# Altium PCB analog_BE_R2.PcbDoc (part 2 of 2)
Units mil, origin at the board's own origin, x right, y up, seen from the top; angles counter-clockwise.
Board outline 3800 x 1200 mil, 2 copper layers (Top Layer, Bottom Layer), stack 62 mil thick; 98 components, 58 nets, 283 pads, 64 vias.
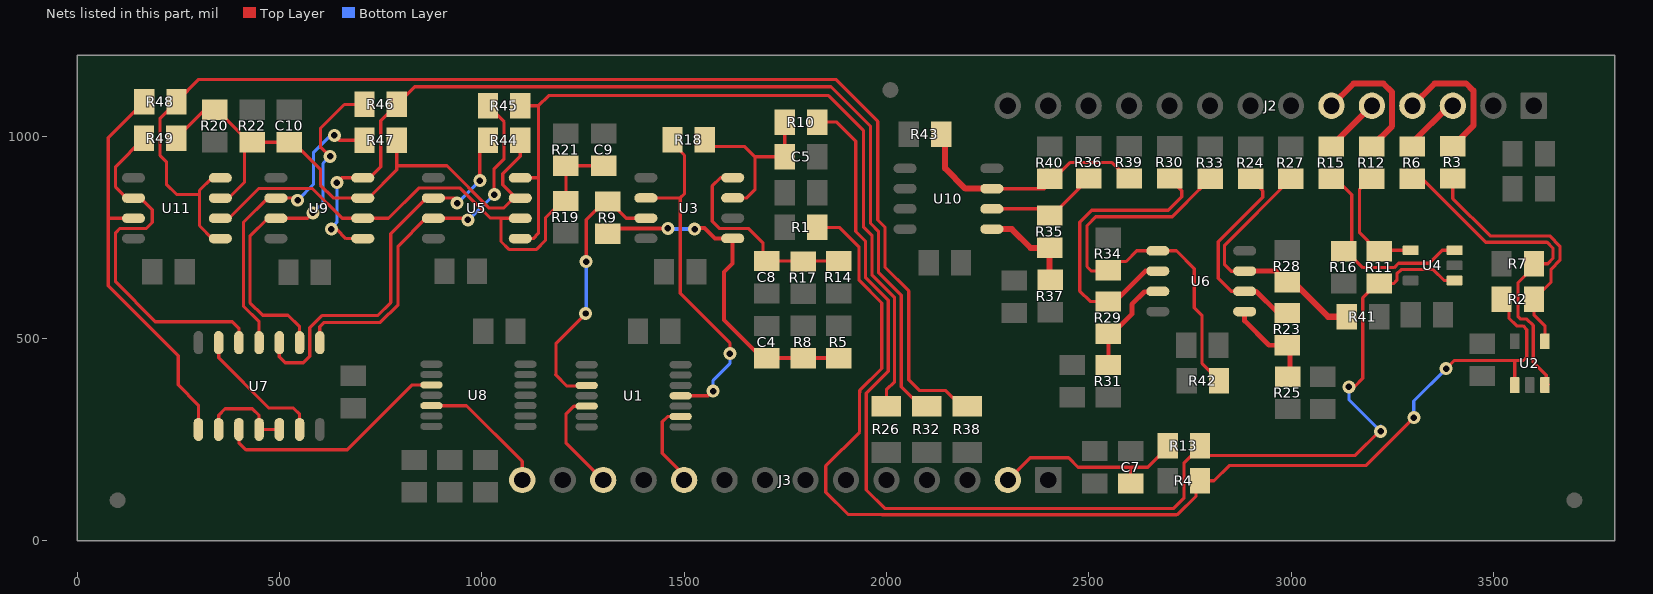
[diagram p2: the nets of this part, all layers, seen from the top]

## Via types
v1: diameter 32, hole 16, Top Layer to Bottom Layer, 54 vias
v2: diameter 40, hole 20, Top Layer to Bottom Layer, 10 vias

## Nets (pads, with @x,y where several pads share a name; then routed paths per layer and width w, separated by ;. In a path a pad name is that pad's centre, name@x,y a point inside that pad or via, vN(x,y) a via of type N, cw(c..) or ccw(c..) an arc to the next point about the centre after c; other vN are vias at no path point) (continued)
NetC4_1: C4.1 R5.1 R8.2 R9.2 U3.1 | length 903.4
  Top Layer w10: R9.2@1302.62,758.47 1315.94,771.8 v1(1459.66,771.8) ; v1(1525.84,770) 1528.22,772.37 1550.76,772.37 1576.02,747.11 U3.1@1620.06,747.11 1620.06,685 1598.69,663.64 1598.69,545.23 1690.27,453.65 C4.1@1690.27,450.96 ; R5.1@1882.6,451.05 1704.02,451.05 C4.1@1703.92,450.96 ; C4.1@1690.27,450.96 1690.27,437.3 C4.1@1703.92,450.96 ; C4.1@1690.27,450.96 C4.1@1703.92,450.96
  Bottom Layer w10: v1(1459.66,771.8) 1461.46,770 v1(1525.84,770)
NetC5_1: C5.1 R10.2 R18.2 U3.3 | length 445.7
  Top Layer w8: R18.2@1551.15,990.85 1567.95,974.05 1650,974.05 1675,949.05 ; U3.3@1620.06,847.11 1655,847.11 1675,867.12 1675,949.05 ; R10.2@1748.88,1034.49 C5.1@1748.88,949.05 1675,949.05
NetC8_1: C8.1 R14.1 R17.2 U3.4 | length 496.1
  Top Layer w8: U3.4@1620.06,897.11 1589.85,897.11 1569.66,876.93 1569.66,789.2 1587.06,771.8 1658.46,771.8 1695,735.26 C8.1@1695,712 ; C8.1@1703.92,691.26 R14.1@1882.6,691.27
NetC9_1: C9.1 R19.1 R21.2 U5.2 U9.2 U11.2 | length 1352.3
  Top Layer w8: U11.2@353.82,796.8 375.2,796.8 448.88,870.49 581.12,870.49 654.8,796.8 U9.2@705.78,796.8 769.39,796.8 844.06,871.47 946.69,871.47 1020.66,797.5 1049.02,797.5 1049.72,796.8 ; U5.2@1095.03,796.8 1049.72,796.8 ; C9.1@1301.58,926.62 R21.2@1207.81,926.62 1207.81,844.12 1203.32,839.63 1198.83,839.63 1157.4,798.2 1157.4,742.05 1135.27,719.92 1066.97,719.92 1047.45,739.44 1047.45,795.94 1048.32,796.8 1049.72,796.8
NetC10_1: C10.1 R20.1 R22.1 R44.2 R47.2 R49.1 U5.3 U9.3 U11.3 | length 1485.4
  Top Layer w8: R49.1@245,994.43 315.57,1065 R20.1@340.37,1065 344.75,1065 424.75,985 R22.1@432.65,985 C10.1@524.61,985 534.45,985 601.19,918.26 601.19,878.81 632.72,847.28 705.31,847.28 U9.3@705.78,846.8 720,846.8 790,916.8 790,926.62 ; U11.3@353.82,846.8 374.01,846.8 413.7,886.5 413.7,920 R22.1@413.7,975.48 ; R47.2@790,990 790,926.62 ; U5.3@1081.98,846.8 1078.34,846.8 1053.65,822.11 1018.5,822.11 913.99,926.62 790,926.62 ; U5.3@1095.03,846.8 1085.11,846.8 1051.9,880.02 1051.9,906.97 1095.03,950.1 R44.2@1095.03,989.91
NetR1_1: R1.1 R2.2 R4.1 U2.1 | length 3017.7
  Top Layer w8: R1.1@1828.88,774.42 1883.12,774.42 1932.38,725.16 1932.38,643.66 1932.5,643.54 1932.5,643.26 1988.25,587.52 1988.25,425.72 1934.13,371.59 1934.13,367.12 1933.58,366.57 1933.58,268.58 1850,185 1850,120 1905,65 1987.95,65 1988.82,64.13 2716.58,64.13 2717.45,65 2720,65 2764.96,109.96 2764.96,148.21 R4.1@2775,148.21 2809.37,148.21 2846.96,185.81 3184.86,185.81 v1(3303.46,304.42) ; v1(3383.1,425.42) 3403.08,445.4 3552.52,445.4 ; R2.2@3520,597.1 3528.49,597.1 3538.51,587.08 3538.51,550.03 3557.56,530.98 3573.27,530.98 3582.58,521.67 3582.58,453.69 3574.29,445.4 3552.52,445.4 ; U2.1@3552.52,384.67 3552.52,445.4
  Bottom Layer w8: v1(3303.46,304.42) 3303.09,304.79 3303.09,345.41 v1(3383.1,425.42)
NetR2_1: R2.1 R3.2 U2.4 | length 635.9
  Top Layer w8: R3.2@3399.66,895 3399.66,845.53 3491.82,753.36 3639.12,753.36 3664.32,728.16 3664.32,692.63 3642.39,670.7 3642.39,639.49 R2.1@3600,597.1 3600,558.55 3627.32,531.23 U2.4@3627.32,492.94
NetR6_2: R6.2 R7.2 U2.3 | length 856.8
  Top Layer w8: R6.2@3299.66,894.53 3323.79,894.53 3480.84,737.48 3632.55,737.48 3647.22,722.81 3647.22,697.99 3634,684.76 R7.2@3600,684.76 3600,676.41 3560.51,636.92 3560.51,554.74 3567.54,547.71 3582.79,547.71 3598.45,532.04 3598.45,441.29 3630.63,409.12 3630.63,391.16 U2.3@3635.85,385.94
  Top Layer w10: U2.3@3627.32,384.67 U2.3@3631.06,380.94
NetR9_1: R9.1 U1.3 U3.7 | length 705.5
  Top Layer w8: v1(1256.66,561.59) 1256.66,560.66 1183.13,487.13 1183.13,410.27 1182.86,410 1210.58,382.28 1257.66,382.28 U1.3@1259.2,383.82 ; v1(1258,690) 1258,793.1 1303.37,838.47 R9.1@1311.63,838.47 ; R9.1@1301.58,824.84 R9.1@1315.21,838.47 ; R9.1@1311.53,838.57 R9.1@1311.63,838.47 ; U3.7@1405.49,797.11 1356.57,797.11 R9.1@1315.21,838.47 ; R9.1@1311.63,838.47 R9.1@1315.21,838.47
  Bottom Layer w8: v1(1256.66,561.59) 1258,562.93 v1(1258,690)
NetR10_1: R10.1 R11.2 R13.1 U4.1 | length 3125.6
  Top Layer w8: R10.1@1828.88,1034.49 1877.17,1034.49 1924.1,987.56 1924.1,764.15 1948.25,740 1948.25,650.24 1948.51,649.98 1948.38,649.84 2004.13,594.09 2004.13,419.14 1950,365.02 1950,125.4 1995.4,80 2710,80 2735,105 2735,191.47 2754.42,210.89 3158.55,210.89 3217.66,270 v1(3221.33,270) ; v1(3142.99,380) 3156.08,380 3177.22,401.14 3177.22,600.04 3212.62,635.43 R11.2@3217.62,635.43 3253.05,635.43 3261.53,643.91 3261.53,659.54 3271.99,670 3351.35,670 3378.26,643.09 U4.1@3403.8,643.09
  Bottom Layer w8: v1(3142.99,380) 3142.99,348.34 3214.63,276.7 3221.33,283.41 v1(3221.33,270)
NetR11_1: R11.1 R12.2 U4.4 | length 295.9
  Top Layer w8: R12.2@3199.66,894.53 3199.66,890 3182.66,873 3173.59,873 3169.16,868.57 3169.16,760.6 3211.87,717.89 U4.4@3295.53,717.89
NetR15_2: R15.2 R16.2 U4.3 | length 530
  Top Layer w8: R15.2@3099.66,894.53 3110.13,894.53 3149.66,855 3149.66,740.43 3124.66,715.43 R16.2@3129.66,715.43 3136.96,715.43 3177.4,675 3254.54,675 3265.41,685.87 3341.21,685.87 3373.23,717.89 U4.3@3403.8,717.89
NetR18_1: R18.1 U1.11 U3.6 | length 875.3
  Top Layer w8: U3.6@1405.49,847.11 1490.42,847.11 ; R18.1@1471.15,990.85 1471.15,981.88 1500.84,952.19 1500.84,857.53 1490.42,847.11 ; U1.11@1491.48,358.23 1559.7,358.23 v1(1571.47,370) ; v1(1613.06,462.25) 1613.06,488.82 1490.42,611.45 1490.42,847.11
  Bottom Layer w8: v1(1571.47,370) 1571.47,396.18 1613.06,437.77 v1(1613.06,462.25)
NetR23_1: R23.1 R24.2 U6.2 | length 510.3
  Top Layer w8: U6.2@2885.16,616.37 2851.68,616.37 2819.71,648.34 2819.71,739.03 2929.66,848.98 2929.66,864.53 R24.2@2899.66,894.53
  Top Layer w12: U6.2@2885.16,616.37 2913.25,616.37 2966.52,563.1 R23.1@2990.51,563.1
NetR23_2: R23.2 R25.1 U6.1 | length 239.9
  Top Layer w12: U6.1@2885.16,566.37 2885.16,543.32 2945.38,483.1 R23.2@2990.51,483.1 2997.45,476.16 R25.1@2997.45,399.44
NetR26_2: R26.2 R45.1 U5.1 U5.4 | length 2027
  Top Layer w8: U5.1@1095.03,746.8 1127.41,746.8 1140,759.4 1140,883.41 1140,897.11 ; U5.4@1095.03,896.8 1139.69,896.8 1140,897.11 ; R45.1@1095.14,1075 1140,1075 ; R26.2@2000,331.89 2000,373.05 2020,393.05 2020,600.94 1964.13,656.81 1964.13,755 1943.1,776.02 1943.1,1013.93 1857.03,1100 1165,1100 1140,1075 ; 1140,897.11 1140,1075
NetR27_2: R27.2 R28.2 R41.2 U6.3 | length 635.9
  Top Layer w8: U6.3@2885.16,666.37 2884.77,665.98 2851.87,665.98 2835.58,682.27 2835.58,730.46 R27.2@2999.66,894.53
  Top Layer w12: U6.3@2885.16,666.37 2962.95,666.37 R28.2@2990.51,638.81
  Top Layer w15: R28.2@2990.51,638.81 3006.19,638.81 3091.4,553.6 R41.2@3137.62,553.6
NetR29_1: R29.1 R30.2 U6.6 | length 764
  Top Layer w8: R29.1@2548.35,591.37 2531.62,574.64 2531.62,591.37 2503.35,591.37 2477.66,617.07 2477.66,787.53 2506.78,816.65 2696.12,816.65 2729.66,850.18 2729.66,865 R30.2@2699.66,895
  Top Layer w12: R29.1@2548.35,591.37 2565.04,591.37 2640.04,666.37 U6.6@2670.59,666.37
NetR29_2: R29.2 R31.1 U6.7 | length 256.8
  Top Layer w10: R31.1@2548.35,434.41 R29.2@2548.35,511.37
  Top Layer w12: R29.2@2548.35,511.65 2565.09,528.39 2574.82,528.39 2606.43,560 2606.43,584.22 2637.62,615.41 2669.64,615.41 U6.7@2670.59,616.37
NetR32_2: R32.2 R46.1 U9.1 U9.4 | length 2492.4
  Top Layer w8: v1(628.43,770) 641.01,770 664.21,746.8 U9.1@705.78,746.8 ; v1(641.88,885) 653.68,896.8 U9.4@705.78,896.8 722.76,896.8 750,924.05 750,1038.08 R46.1@790,1078.07 833.97,1122.04 1862.96,1122.04 1960.55,1024.45 1960.55,784.45 1980,765 1980,663.39 2036.31,607.07 2036.31,380.65 2085.07,331.89 R32.2@2100,331.89
  Bottom Layer w8: v1(628.43,770) 631.44,770 636.23,774.79 636.23,781.03 641.88,786.68 v1(641.88,885)
NetR33_2: R33.2 R34.2 R42.2 U6.5 | length 1064.2
  Top Layer w8: R33.2@2799.76,894.53 2743.53,838.3 2743.53,838.12 2706.19,800.77 2517.35,800.77 2495.53,778.95 2495.53,677.52 2506.68,666.37 2546.02,666.37 R34.2@2548.35,668.7 2569.65,690 2592.11,690 2618.48,716.37 U6.5@2670.59,716.37 2716.72,716.37 2760.8,672.29 2760.8,575.37 2780,556.17 2780,437.9 R42.2@2821.94,395.95
NetR35_1: R35.1 R36.2 U10.2 | length 283.7
  Top Layer w8: U10.2@2260.46,820.15 2386.92,820.15 R35.1@2403.18,803.89 2408.98,809.69 2414.35,809.69 R36.2@2499.66,895
NetR35_2: R35.2 R37.1 U10.1 | length 241.6
  Top Layer w15: U10.1@2260.46,770.15 2309.65,770.15 2355.91,723.89 R35.2@2403.18,723.89 2403.18,646.29 R37.1@2404.66,644.81
NetR38_2: R38.2 R48.1 U11.1 U11.4 | length 3176.4
  Top Layer w8: U11.1@353.82,746.8 334.35,746.8 302.38,778.78 302.38,855.61 ; U11.4@353.82,896.8 333.36,896.8 302.38,865.82 302.38,855.61 ; R38.2@2199.66,331.89 2185.48,331.89 2146.21,371.16 2081.85,371.16 2055,398.01 2055,617.38 1996.31,676.07 1996.31,775 1978.68,792.63 1978.68,1036.32 1875,1140 300.63,1140 R48.1@245.63,1085 205,1044.37 205,951.88 220.58,936.3 220.58,880.83 245.81,855.61 302.38,855.61
NetR39_2: R39.2 R40.2 R43.2 U10.3 | length 618.7
  Top Layer w8: U10.3@2260.46,870.15 2389.73,870.15 R40.2@2403.18,883.6 ; R40.2@2403.18,894.53 R40.2@2403.18,883.6 ; R39.2@2599.66,895 2596.27,895 2556.27,935 2454.58,935 R40.2@2403.18,883.6
  Top Layer w15: R43.2@2135.22,1005 2145,995.22 2145,920 2194.85,870.15 U10.3@2260.46,870.15
NetR44_1: R44.1 U5.6 U7.3 | length 1026.9
  Top Layer w8: U7.3@499.66,489.57 499.66,454.62 514.46,439.82 558.61,439.82 574.66,455.87 574.66,526.66 603.29,555.29 603.85,555.29 605.26,556.71 743.05,556.71 775,588.66 775,758.79 863.01,846.8 U5.6@880.46,846.8 933.5,846.8 939,841.31 v1(939,834.19) ; v1(995,890) 995,1009.93 R44.1@1015.03,989.91
  Bottom Layer w8: v1(939,834.19) 939.19,834.19 v1(995,890)
NetR45_2: R45.2 U5.7 U7.1 | length 946.8
  Top Layer w8: U7.1@599.66,489.57 599.66,528.66 610.42,539.42 749.52,539.42 793,582.9 793,728.08 861.72,796.8 U5.7@880.46,796.8 961.62,796.8 v1(965.54,792.88) v1@968.51,795.85 ; R45.2@1015.14,1075 1055,1035.14 1055,943.58 1030,918.58 1030,864.54 1030.93,865.47 v1(1030.93,855.61)
  Bottom Layer w8: v1(965.54,792.88) 968.2,792.88 v1(1030.93,855.61)
NetR46_2: R46.2 U7.2 U9.7 | length 899.4
  Top Layer w8: U7.2@549.66,489.57 549.66,528.73 521.1,557.29 458.3,557.29 427,588.58 427,752.26 471.54,796.8 U9.7@491.21,796.8 569.51,796.8 v1(582.7,810) ; v1(625,950) 601.19,973.81 601.19,1018.75 660.51,1078.07 R46.2@710,1078.07
  Bottom Layer w8: v1(582.7,810) 607.49,834.79 607.49,932.49 v1(625,950)
NetR47_1: R47.1 U7.4 U9.6 | length 756.4
  Top Layer w8: U7.4@449.66,489.57 449.66,540.98 411.13,579.51 411.13,786.86 471.07,846.8 U9.6@491.21,846.8 539.68,846.8 v1(545,841.49) ; v1(635.74,1001.74) 647.48,990 R47.1@710,990
  Bottom Layer w8: v1(545,841.49) 583.85,880.34 583.85,958.85 626.74,1001.74 v1(635.74,1001.74)
NetR48_2: R48.2 U7.8 U11.7 | length 975.2
  Top Layer w8: 79.08,797.17 U11.7@115.33,797.17 ; R48.2@165.63,1085 76.95,996.31 76.95,630.41 249.98,457.38 249.98,385 299.66,335.33 U7.8@299.66,275
NetR49_2: R49.2 U7.5 U11.6 | length 905.9
  Top Layer w8: R49.2@165,994.43 95,924.43 95,873.99 122.19,846.8 U11.6@139.25,846.8 157.46,846.8 185.81,818.45 185.81,786.45 170.98,771.63 105.04,771.63 95,761.59 95,639.56 193.14,541.42 383.24,541.42 399.66,525 U7.5@399.66,489.57
NetU7_6: U7.6 U7.13 | length 332.9
  Top Layer w8: U7.6@349.66,489.57 349.66,451.84 473.5,328 534,328 549.66,312.34 U7.13@549.66,275
NetU7_9: U7.9 U7.11 U7.12 | length 233.7
  Top Layer w8: U7.9@349.66,275 349.66,310.66 365.42,326.42 432.68,326.42 449.66,309.44 U7.11@449.66,275 U7.12@499.66,275
NetU7_10: U7.10 U8.3 | length 582
  Top Layer w8: U7.10@399.66,275 399.66,242.34 417,225 667.71,225 827.71,385 U8.3@875.53,385
OCP_Latch: J3.14 U8.5 | length 327.5
  Top Layer w8: U8.5@875.53,333.82 962.1,333.82 1100,195.92 J3.14@1100,150
OTP_Latch: J3.12 U1.5 | length 260.6
  Top Layer w8: U1.5@1259.2,332.64 1227.64,332.64 1207.81,312.81 1207.81,242.19 J3.12@1300,150
OVP_Latch: J3.10 U1.9 | length 217.2
  Top Layer w8: U1.9@1491.48,307.05 1459.01,307.05 1446.11,294.15 1446.11,216.12 1500,162.22 J3.10@1500,150
Temp_N: J2.4 R3.1 | length 338.9
  Top Layer w15: J2.4@3299.66,1075 3354.66,1130 3432.3,1130 3450.3,1112 3450.3,1025.65 R3.1@3399.66,975
Temp_P: J2.3 R6.1 | length 147.3
  Top Layer w15: R6.1@3299.66,974.53 3299.66,984.15 3390.51,1075 J2.3@3399.66,1075
Vdc_N: J2.6 R12.1 | length 336.2
  Top Layer w15: J2.6@3099.66,1075 3154.66,1130 3227.95,1130 3249.57,1108.37 3249.57,1024.45 R12.1@3199.66,974.53
Vdc_P: J2.5 R15.1 | length 141.9
  Top Layer w15: R15.1@3099.66,974.53 3199.66,1074.53 J2.5@3199.66,1075
VdcFbk: C7.1 J3.2 R13.2 | length 492.1
  Top Layer w8: J3.2@2300,150 2355,205 2450,205 2473.28,181.72 2603.26,181.72 ; C7.1@2603.26,141.72 2603.26,181.72 ; R13.2@2695,235 2695,230.58 2646.15,181.72 2603.26,181.72
pads on no net: FID1.1 FID2.1 FID3.1 U1.6 U1.8 U8.6 U8.8 U8.9 U8.10 U8.11 U8.12 U8.13 U10.5 U10.6 U10.7

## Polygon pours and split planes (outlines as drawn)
GND on Bottom Layer "BOTTOM_LAYER_GND_P000" (solid, remove dead copper, pour order 0): 3700,50 3750,100 3750,1100 3700,1150 100.87,1150 50,1099.13 50,100 100,50
3.3V on Top Layer "TOP_LAYER_3.3V_P008" (solid, remove dead copper, pour order 8): 810,563.1
3.3V on Top Layer "TOP_LAYER_3.3V_P006" (solid, remove dead copper, pour order 6): 1512.76,287.46 272.54,287.46 55,505 55,740 1490.49,740 1512.76,717.74
3.3V on Top Layer "TOP_LAYER_3.3V_P004" (solid, remove dead copper, pour order 4): 3499.66,1075 3714.81,1075 3750,1039.81 3750,194.33 3605.67,50 1578.02,50 1485.96,142.06 1485.96,730.66 2393.25,730.66 2742.59,1080 3425,1080

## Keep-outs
Keep-Out Layer:
  text ".Layer_Name" at 577,-858.49 h60

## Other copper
Top Layer:
  text ".Layer_Name" at 577,-858.49 h60
Bottom Layer:
  text ".Layer_Name" at 577,-858.49 h60

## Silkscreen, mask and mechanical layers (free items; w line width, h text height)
Top Overlay:
  text "GND  GND  ICN    ICP    IBN    IBP    IAN    IAP     VN     VP     TN     TP     3V3    GND" at 2267.23,1122.04 h40
  text "ANALOG FE" at 2902.71,110.51 h80
  text "OCP  Cocp  OTP   Cotp  OVP  Covp  GND  GND  GND    IC       IB       IA     VDC    T" at 1064.51,68.47 h40
  text "'.PRJ_Number'.PCB_Rev" at 2902.71,35.51 h70
  text ".Layer_Name" at 577,-858.49 h60
Bottom Overlay:
  text ".Layer_Name" at 577,-858.49 h60
Top Paste:
  text ".Layer_Name" at 577,-858.49 h60
Bottom Paste:
  text ".Layer_Name" at 577,-858.49 h60
Top Solder:
  text ".Layer_Name" at 577,-858.49 h60
  text ".Layer_Name" at 577,-858.49 h60
Bottom Solder:
  text ".Layer_Name" at 577,-858.49 h60
Drill Guide:
  text ".Layer_Name" at 577,-858.49 h60
M1 Board Outline:
  the board outline again, w10
  text ".Layer_Name" at 577,-858.49 h60
M2 Board Dimensions:
  rectangle: 0,-275 125,-150
  rectangle: 125,-400 500,-275
  lines w7: 0,-275 1000,-275 ; 125,-400 125,-150 ; 250,-400 250,-150 ; 500,-400 500,-150 ; 750,-400 750,-150 ; 0,-400 1000,-400 1000,-150 0,-150 0,-400
  text ".Layer_Name" at 577,-858.49 h60
M3 3D STEP Top:
  text ".Layer_Name" at 577,-858.49 h60
M4 3D STEP Bottom:
  text ".Layer_Name" at 577,-858.49 h60
M5 Assembly Top:
  lines w10: -292,-930.17 6308,-930.17 ; -292,-726.83 6310,-726.83 ; -292,-523.5 -292,-1133.5 3713,-1133.5 6310,-1133.5 6310,-523.5 -291.5,-523.5 -291.5,-1133.5 1284,-1133.5 ; 2173,-1133.5 2173,-523.5 ; 3440,-726.83 3440,-523.5 ; 4280,-726.83 4280,-523.5 ; 4902,-1140 4902,-937.17
  text "COMPONENTS MARKED 'DNP' SHOULD NOT BE POPULATED." at 1153.5,-318.5 h60
  text "ASSEMBLY VARIANT:" at 1153,-434 h60
  text ".VariantName" at 2189,-434 h60
  text "PCB VIEWED FROM TOP SIDE" at -228.5,-655.67 h60
  text "BOARD #:" at 2248,-655.67 h60
  text ".PRJ_Number" at 2793.5,-655.67 h60
  text "REV:" at 3638,-655.67 h60
  text ".PCB_Rev" at 3929.5,-655.67 h60
  text "SVN REV:" at 4476,-655.67 h60
  text ".VersionControl_RevNumber" at 4982,-655.67 h60
  text "TID #:" at 2248,-859 h60
  text ".TID" at 2793.5,-859 h60
  text "PLOT NAME =" at -228.5,-1064.34 h60
  text ".plot_File_Name" at 577,-1064.34 h60
  text "GENERATED    :" at 2250,-1064.34 h60
  text ".Print_Date" at 3119.5,-1064.34 h60
  text ".Print_Time" at 3848.5,-1064.34 h60
  text "TEXAS INSTRUMENTS" at 5113,-1064.34 h60
M6 Assembly Bottom:
  lines w10: -292.5,-727.33 6309.5,-727.33 ; -290.5,-930.67 6309.5,-930.67 ; 1115.5,-1140.5 1115.5,-937.67 ; 1737.5,-727.33 1737.5,-524 ; 2577.5,-727.33 2577.5,-524 ; 3844.5,-1134 3844.5,-524 ; 4733.5,-1134 6309,-1134 6309,-524 -292.5,-524 -292.5,-1134 2304.5,-1134 6309.5,-1134 6309.5,-524
  text "COMPONENTS MARKED 'DNP' SHOULD NOT BE POPULATED." at 6102,-318 h60
  text ".VariantName" at 5058,-434 h60
  text "ASSEMBLY VARIANT:" at 6097,-434 h60
  text ".VersionControl_RevNumber" at 1035.5,-656.17 h60
  text "SVN REV:" at 1541.5,-656.17 h60
  text ".PCB_Rev" at 2088,-656.17 h60
  text "REV:" at 2379.5,-656.17 h60
  text ".PRJ_Number" at 3224,-656.17 h60
  text "BOARD #:" at 3769.5,-656.17 h60
  text "PCB VIEWED FROM BOTTOM SIDE" at 6246,-656.17 h60
  text ".TID" at 3224,-859.5 h60
  text "TID #:" at 3769.5,-859.5 h60
  text "TEXAS INSTRUMENTS" at 904.5,-1064.84 h60
  text ".Print_Time" at 2169,-1064.84 h60
  text ".Print_Date" at 2898,-1064.84 h60
  text "GENERATED    :" at 3767.5,-1064.84 h60
  text ".plot_File_Name" at 5440.5,-1064.84 h60
  text "PLOT NAME =" at 6246,-1064.84 h60
M9 Title Sheet:
  drawing of 57 lines, arcs and shapes, not listed
  text "1" at 739.84,8036.5 h70
  text "2" at 3235.5,8036.5 h70
  text "3" at 5724.84,8036.5 h70
  text "4" at 8231.51,8036.5 h70
  text "5" at 10730.5,8036.5 h70
  text "6" at 13235.5,8036.5 h70
  text "A" at -416.5,6893.5 h70
  text "A" at 14383.5,6893.5 h70
  text "B" at -416.5,4513.5 h70
  text "B" at 14383.5,4513.5 h70
  text "C" at -416.5,2138.5 h70
  text "C" at 14383.5,2138.5 h70
  text "PROJECT TITLE:" at 11343.5,277.5 h45
  text ".PRJ_Title" at 11393.5,144.17 h70
  text "DESIGNED FOR:" at 11343.5,-23.5 h45
  text ".PRJ_Customer" at 11393.5,-163.5 h70
  text "D" at -416.5,-231.5 h70
  text "D" at 14383.5,-231.5 h70
  text "FILE NAME:" at 11343.5,-323.5 h45
  text ".PCB_File_Name_No_Path" at 11393.5,-443.5 h70
  text "Texas Instruments (TI) and/or its licensors do not warrant the accuracy or completeness of this specification" at 6374,-605.34 h45
  text "ENGINEER:" at 11343.5,-613.5 h45
  text "LAYOUT BY:" at 12848.5,-613.5 h45
  text "or any information contained therein. TI and/or its licensors do not warrant that this design will meet" at 6329.01,-718 h45
  text ".PRJ_Engineer" at 11393.5,-768.49 h70
  text ".PCB_Layout" at 12899,-768.49 h70
  text "the specifications, will be suitable for your application or fit for any particular purpose, or will operate in" at 6329.01,-830.67 h45
  text ".Layer_Name" at 577,-858.49 h60
  text "ALTIUM DESIGNER VERSION:" at 12848.5,-923.5 h45
  text "an implementation. TI and/or its licensors do not warrant that the design is production worthy. You should" at 6329.01,-943.33 h45
  text "completely validate and test your design implementation to confirm the system functionality for your application." at 6374,-1056 h45
  text ".print_Scale" at 11393.5,-1056.83 h70
  text ".Application_BuildNumber" at 12899,-1056.83 h70
  text "1" at 739.84,-1263.5 h70
  text "2" at 3235.5,-1263.5 h70
  text "3" at 5724.84,-1263.5 h70
  text "4" at 8231.51,-1263.5 h70
  text "5" at 10730.5,-1263.5 h70
  text "6" at 13235.5,-1263.5 h70
M10 Fab Notes:
  drawing of 189 lines, arcs and shapes, not listed
  text "DESIGN INFORMATION" at 12382.02,6356.17 h60
  text "MIN. TRACK WIDTH:" at 11737.46,6224.05 h60
  text "8" at 12833.7,6224.05 h60
  text "MIL" at 12988.46,6224.05 h60
  text "MIN. CLEARANCE:" at 11737.46,6099.92 h60
  text "0.2" at 12773.7,6099.93 h60
  text "mm" at 12988.46,6099.92 h60
  text "MIN. VIA PAD SIZE:" at 11737.46,5975.8 h60
  text "24" at 12803.71,5975.8 h60
  text "MIL" at 12988.46,5975.8 h60
  text "0.05mm (2MIL)" at 12432.46,5845.9 h60
  text "MINIMUM ANNULAR RING" at 11408.23,5837.67 h60
  text "EXTERNAL" at 13140.46,5837.67 h60
  text "PER" at 11608.23,5727.55 h60
  text "IPC-D-275 CLASS 2 LEVEL C" at 11828.23,5727.54 h60
  text "MIL, HOLES" at 13316.46,5627.07 h60
  text "+/-" at 12924,5618.48 h60
  text "+/-" at 13778,5618.48 h60
  text "REGISTRATION TOLERANCES:" at 11408.23,5617.42 h60
  text "METAL" at 12608,5617.42 h60
  text "5" at 13184.2,5617.42 h60
  text "3" at 14017.2,5617.42 h60
  text "MIL" at 14133.46,5617.42 h60
  text "HOLE SIZE TOLERANCE (UNLESS OTHERWISE SPECIFIED):" at 11408.23,5519.1 h60
  text "+/-" at 13778,5516.23 h60
  text "3" at 14017.2,5515.17 h60
  text "MIL" at 14133.46,5515.17 h60
  text "MATERIAL:" at 11333.46,5377.52 h60
  text "FR-4 High Tg" at 12319.9,5249 h60
  text "X" at 12175.46,5241.01 h60
  text "FR-408" at 11754.46,5236.49 h60
  text "OTHER" at 13242.46,5236.49 h60
  text "62 MIL (1.6mm) +/-10%" at 12074.56,5093.46 h60
  text "X" at 11954.46,5091.01 h60
  text "THICKNESS:" at 11408.23,5085.24 h60
  text "OTHER" at 13359.46,5085.24 h60
  text "TOLERANCE:" at 11408.23,4946.92 h60
  text "X" at 12256.46,4946.92 h60
  text "ANSI IPC-6012 TYPE 3 CLASS 2" at 12434.48,4946.92 h60
  text "OTHER +/-" at 12434.46,4802.73 h60
  text "BOW & TWIST:" at 11408.23,4657.54 h60
  text "X" at 12256.46,4657.54 h60
  text "ANSI IPC-6012 TYPE 3 CLASS 2" at 12434.48,4657.54 h60
  text "OTHER +/-" at 12434.46,4510.85 h60
  text "DRILLING:" at 11333.46,4380.23 h60
  text "NC_DRILL FILES" at 13094.46,4275.04 h60
  text "REFERENCE:" at 11408.23,4271.1 h60
  text "X" at 12065.46,4271.01 h60
  text "AS SHOWN" at 12243.46,4271.1 h60
  text "X" at 12966.46,4271.1 h60
  text "OTHER" at 13392.46,4128.85 h60
  text "PTH COPPER THICKNESS:" at 11407.91,4125.32 h60
  text "X" at 12547.14,4125.32 h60
  text "20-30 um" at 12675.14,4125.32 h60
  text "BOARD FINISH:" at 11333.46,3977.73 h60
  text "SILKSCREEN:" at 11488.68,3867.6 h60
  text "X" at 12446.46,3867.6 h60
  text "TOP" at 12563.46,3867.6 h60
  text "X" at 12956.46,3867.6 h60
  text "BOTTOM" at 13074.46,3867.6 h60
  text "SILKSCREEN COLOR:" at 11488.68,3712.41 h60
  text "X" at 12445.46,3712.41 h60
  text "WHITE" at 12563.46,3712.41 h60
  text "OTHER" at 13074.46,3712.41 h60
  text "X" at 12576.46,3568.96 h60
  text "GREEN" at 12694.46,3568.96 h60
  text "OTHER" at 13312.46,3568.96 h60
  text "SOLDER RESIST COLOR:" at 11488.68,3562.1 h60
  text "X" at 12576.46,3414.71 h60
  text "MATTE" at 12694.46,3414.71 h60
  text "SEMI-GLOSS" at 13312,3414.07 h60
  text "IMMERSION GOLD (ENIG)" at 12394.46,3241.94 h60
  text "ENEPIG" at 13732,3234.72 h60
  text "SURFACE FINISH:" at 11333.46,3233.72 h60
  text "X" at 12216.46,3233.72 h60
  text "IMM. TIN/SILVER OR EQUIV" at 11663,3096.4 h60
  text "OTHER" at 13094.46,3092.47 h60
  text "ARRAY/PANEL:" at 11333.46,2937.09 h60
  text "CUT AND TRIM PER M1 BOARD OUTLINE" at 12394.46,2928.87 h60
  text "N.C. ROUTE" at 12394.46,2792.9 h60
  text "X" at 13082.46,2792.9 h60
  text "V. SCORE" at 13260.46,2792.9 h60
  text "CERTIFICATION:" at 11333.46,2663.77 h60
  text "MATERIALS AND WORKMANSHIP FOR ALL PCBS" at 12058.46,2663.77 h60
  text "TO MEET OR EXCEED THE REQUIREMENTS OF:" at 12058.46,2569.71 h60
  text "X" at 11695.97,2441.08 h60
  text "ANSI IPC-A-600F CLASS ->" at 11823.96,2441.08 h60
  text "X" at 13471.97,2441.08 h60
  text "2" at 13581.96,2441.08 h60
  text "1" at 13266.96,2439.58 h60
  text "3" at 13935.96,2439.58 h60
  text "X" at 12507.97,2293.39 h60
  text "RoHS" at 12635.96,2293.39 h60
  text "OTHER" at 13280.36,2293.39 h60
  text "PER ORDER" at 13677.42,2293.39 h60
  text "ALL BOARDS MUST MEET OR EXCEED UL94-V0 REQUIREMENTS." at 11361,2139.57 h60
  text "PCB MUST BEAR THE UL94V-0 UL REGISTERED MATERIAL ID NUMBER" at 11361,2023.5 h60
  text "ADDITIONAL REQUIREMENTS:" at 11333.46,1854.08 h60
  text "MICROSECTION:" at 11408.23,1746.95 h60
  text "YES" at 12313.96,1746.95 h60
  text "REQUIRED" at 13175.46,1602.62 h60
  text "BARE BOARD ELEC. TEST:" at 11408.23,1599.76 h60
  text "NONE" at 12713.96,1599.76 h60
  text "X" at 13057.46,1599.76 h60
  text "PER ORDER" at 13767.46,1599.76 h60
  text "XX MIL VIAS REQUIRE NON-CONDUCTIVE FILL AND PLANARIZE" at 11576.38,1394.82 h59
  text "XX MIL VIAS REQUIRE CONDUCTIVE FILL AND PLANARIZE" at 11584.38,1290.84 h60
  text "OUTER XX MIL TRACES REQUIRE 50 OHM SINGLE-ENDED IMPEDANCE" at 11583.39,1127.46 h58
  text "LAYER 2 & 3 (INNER LAYERS) XX MIL WIDE, XX MIL SPACE / TRACES REQUIRE 100 OHM DIFFERENTIAL IMPEDANCE" at 11575.39,891.74 h60
  text ".Layer_Name" at 577,-858.49 h60
M11 Gerber Information:
  lines w10: -292,-930.17 6308,-930.17 ; -292,-726.83 6310,-726.83 ; -292,-523.5 -292,-1133.5 3713,-1133.5 6310,-1133.5 6310,-523.5 -291.5,-523.5 -291.5,-1133.5 1284,-1133.5 ; 2173,-1133.5 2173,-523.5 ; 3440,-726.83 3440,-523.5 ; 4280,-726.83 4280,-523.5 ; 4902,-1140 4902,-937.17
  text "ALL ARTWORK VIEWED FROM TOP SIDE" at -228.5,-655.67 h60
  text "BOARD #:" at 2248,-655.67 h60
  text ".PRJ_Number" at 2793.5,-655.67 h60
  text "REV:" at 3638,-655.67 h60
  text ".PCB_Rev" at 3929.5,-655.67 h60
  text "SVN REV:" at 4476,-655.67 h60
  text ".VersionControl_RevNumber" at 4982,-655.67 h60
  text "LAYER NAME =" at -228.5,-858.49 h60
  text "TID #:" at 2248,-859 h60
  text ".TID" at 2793.5,-859 h60
  text "PLOT NAME =" at -228.5,-1064.34 h60
  text ".plot_File_Name" at 577,-1064.34 h60
  text "GENERATED    :" at 2250,-1064.34 h60
  text ".Print_Date" at 3119.5,-1064.34 h60
  text ".Print_Time" at 3848.5,-1064.34 h60
  text "TEXAS INSTRUMENTS" at 5113,-1064.34 h60
M12 Stackup:
  drawing of 191 lines, arcs and shapes, not listed
  text "Layer" at 9811.59,7582.44 h60
  text "Name" at 10221.51,7582.44 h60
  text "Material" at 11151.25,7582.44 h60
  text "Thickness" at 12011.02,7582.44 h60
  text "Constant" at 12660.85,7582.44 h60
  text "Board Layer Stack" at 13230.71,7582.44 h60
  text "1" at 9811.59,7462.44 h60
  text "Top Overlay" at 10221.51,7462.44 h60
  text "2" at 9811.59,7342.44 h60
  text "Top Solder" at 10221.51,7342.44 h60
  text "Solder Resist" at 11151.25,7342.44 h60
  text "0.40mil" at 12011.02,7342.44 h60
  text "3.5" at 12660.85,7342.44 h60
  text "3" at 9811.59,7222.44 h60
  text "Top Layer" at 10221.51,7222.44 h60
  text "Copper" at 11151.25,7222.44 h60
  text "1.40mil" at 12011.02,7222.44 h60
  text "4" at 9811.59,7102.44 h60
  text "Dielectric1" at 10221.51,7102.44 h60
  text "FR-4" at 11151.25,7102.44 h60
  text "59.20mil" at 12011.02,7102.44 h60
  text "4.8" at 12660.85,7102.44 h60
  text "5" at 9811.59,6982.44 h60
  text "Bottom Layer" at 10221.51,6982.44 h60
  text "Copper" at 11151.25,6982.44 h60
  text "1.40mil" at 12011.02,6982.44 h60
  text "6" at 9811.59,6862.44 h60
  text "Bottom Solder" at 10221.51,6862.44 h60
  text "Solder Resist" at 11151.25,6862.44 h60
  text "0.40mil" at 12011.02,6862.44 h60
  text "3.5" at 12660.85,6862.44 h60
  text "7" at 9811.59,6742.44 h60
  text "Bottom Overlay" at 10221.51,6742.44 h60
  text ".Layer_Name" at 577,-858.49 h60
M13 Component Bodies Top:
  text ".Layer_Name" at 577,-858.49 h60
M14 Component Bodies Bottom:
  text ".Layer_Name" at 577,-858.49 h60
M15 Courtyards Top:
  text ".Layer_Name" at 577,-858.49 h60
M16 Courtyards Bottom:
  text ".Layer_Name" at 577,-858.49 h60
Drill Drawing:
  circle w10: c4019.7,699.2 r27.63
  lines w10: 3992.07,422.94 4047.32,422.94 4047.32,478.19 3992.07,478.19 3992.07,422.94 ; 3992.07,561.07 4005.88,561.07 4019.7,547.26 4033.51,561.07 4047.32,561.07 4033.51,574.88 4047.32,588.7 4033.51,588.7 4019.7,602.51 4005.88,588.7 3992.07,588.7 4005.88,574.88 3992.07,561.07
  lines w12: 3941.98,385.64 7173.47,385.64 ; 3941.98,758.6 7173.47,758.6 ; 4279.84,261.32 4279.84,882.92 ; 4611.84,261.32 4611.84,882.92 ; 5248.41,261.32 5248.41,882.92 ; 5507.55,261.32 5507.55,882.92 ; 5882.7,261.32 5882.7,882.92 ; 6607.03,261.32 6607.03,882.92 ; 3941.98,261.32 7173.47,261.32 7173.47,882.92 3941.98,882.92 3941.98,261.32
  text "Symbol" at 4016.57,795.9 h72
  text "Quantity" at 4317.14,795.9 h72
  text "Finished Hole Size" at 4649.14,795.9 h72
  text "Plated" at 5285.7,795.9 h72
  text "Hole Type" at 5544.84,795.9 h72
  text "Drill Layer Pair" at 5920,795.9 h72
  text "Hole Tolerance" at 6644.33,795.9 h72
  text "54" at 4317.14,671.58 h60
  text "16.00mil (0.406mm)" at 4649.14,671.58 h60
  text "PTH" at 5285.7,671.58 h60
  text "Round" at 5544.84,671.58 h60
  text "Top Layer - Bottom Layer" at 5920,671.58 h60
  text "10" at 4317.14,547.26 h60
  text "20.00mil (0.508mm)" at 4649.14,547.26 h60
  text "PTH" at 5285.7,547.26 h60
  text "Round" at 5544.84,547.26 h60
  text "Top Layer - Bottom Layer" at 5920,547.26 h60
  text "28" at 4317.14,422.94 h60
  text "40.00mil (1.016mm)" at 4649.14,422.94 h60
  text "PTH" at 5285.7,422.94 h60
  text "Round" at 5544.84,422.94 h60
  text "Top Layer - Bottom Layer" at 5920,422.94 h60
  text "92 Total" at 4317.14,298.62 h60
  text ".Layer_Name" at 577,-858.49 h60
M17 Embedded Cavity:
  text ".Layer_Name" at 577,-858.49 h60
M18 Embedded Assembly:
  text ".Layer_Name" at 577,-858.49 h60
M19 Embedded Keepout:
  text ".Layer_Name" at 577,-858.49 h60

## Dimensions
0,-400 to 1000,-400 on M2 Board Dimensions
0,1200 to 3800,0 on M2 Board Dimensions
3800,1200 to 0,1200 on M2 Board Dimensions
